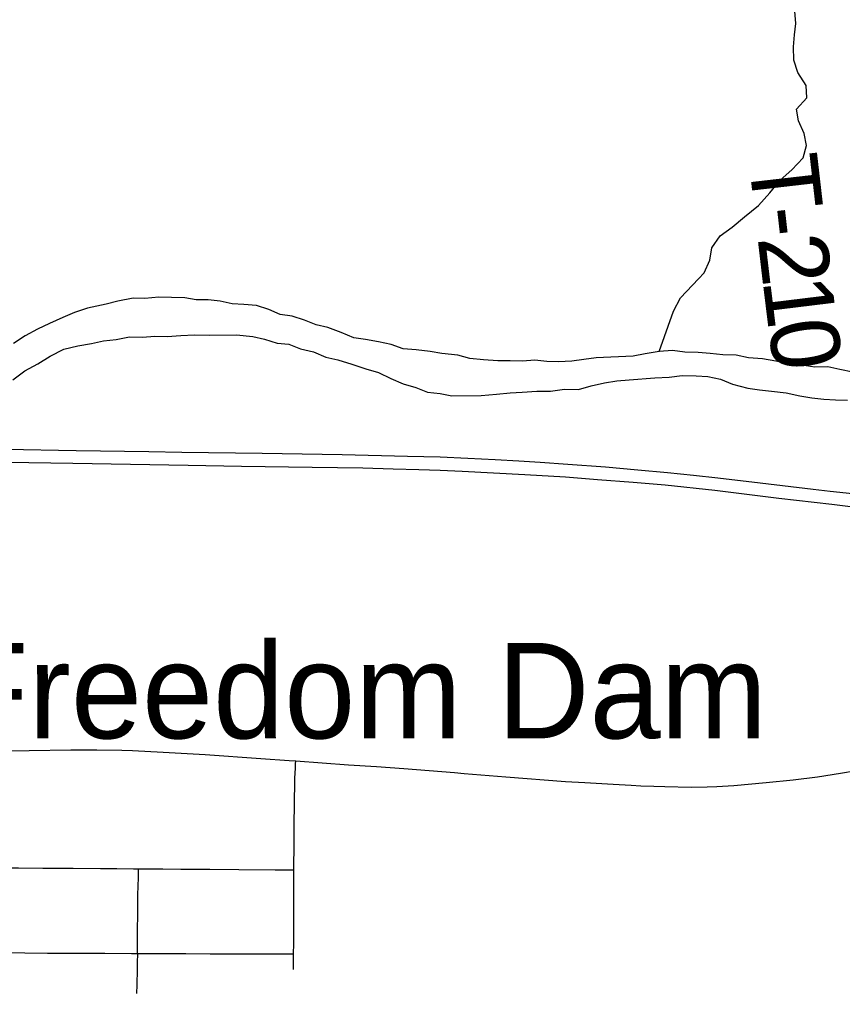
# Model space of a CAD drawing. Extents: x 0 to 34, y 0 to 22.
# Drawn here: x 14.031 to 14.711, y 18.319 to 19.125 of the extents above; entities that cross this region are included whole.
import ezdxf

# ---------------------------------------------------------------- set-up
doc = ezdxf.new("R2010")
doc.units = 0
for name, color, linetype in [('GM_X_Interstate_Route', 7, 'Continuous'), ('GM_X_Major_River', 7, 'Continuous'), ('GM_X_Minor_River', 7, 'Continuous'), ('GM_X_State_Route', 7, 'Continuous'), ('GM_X_Township_Road', 7, 'Continuous'), ('GM_X_Township_Road_Text', 7, 'Continuous'), ('GM_X_Unincorporated_Text', 7, 'Continuous')]:
    doc.layers.add(name, color=color, linetype=linetype)

msp = doc.modelspace()

# ---------------------------------------------------------------- linework, layer by layer
at = {"layer": 'GM_X_Interstate_Route'}
for points in [[(14.01976, 18.7694), (14.07788, 18.76845), (14.13792, 18.76746), (14.16514, 18.76709), (14.23153, 18.76605), (14.29764, 18.76501), (14.35159, 18.76379), (14.37868, 18.76305), (14.40152, 18.76197), (14.4241, 18.76092), (14.44354, 18.75971), (14.46118, 18.75865), (14.48406, 18.75715), (14.51516, 18.75474), (14.54207, 18.75248), (14.56644, 18.75023), (14.58797, 18.74798), (14.60815, 18.74572), (14.64314, 18.74167), (14.68695, 18.73642), (14.70095, 18.73479), (14.71924, 18.73266)], [(13.99038, 18.75888), (14.03863, 18.75832), (14.07493, 18.7579), (14.17041, 18.75624), (14.21428, 18.75549), (14.27278, 18.75462), (14.3148, 18.75392), (14.33985, 18.75324), (14.36103, 18.75261), (14.37867, 18.75209), (14.39666, 18.75136), (14.4486, 18.74848), (14.48222, 18.74644), (14.50857, 18.74428), (14.53819, 18.74205), (14.56458, 18.73985), (14.60559, 18.73563), (14.65837, 18.72905), (14.70224, 18.72398), (14.76361, 18.71623)]]:
    msp.add_lwpolyline(points, dxfattribs=at)
at = {"layer": 'GM_X_Major_River'}
for points in [[(14.24642, 18.88083), (14.23693, 18.88493), (14.22668, 18.88826), (14.21646, 18.88894), (14.20661, 18.88962), (14.19675, 18.89183), (14.1869, 18.89289), (14.17707, 18.89281), (14.16759, 18.89464), (14.15661, 18.89493), (14.14601, 18.89523), (14.13466, 18.89401), (14.12482, 18.89431), (14.11235, 18.89194), (14.10253, 18.88921), (14.08704, 18.88606), (14.07647, 18.88256), (14.06666, 18.87831), (14.05572, 18.8733), (14.04591, 18.86867), (14.03574, 18.86328), (14.02594, 18.85676)], [(14.71952, 18.83323), (14.70891, 18.83543), (14.69905, 18.83763), (14.68808, 18.83716), (14.67747, 18.83898), (14.6661, 18.84003), (14.65587, 18.84223), (14.64488, 18.84404), (14.63351, 18.84509), (14.62328, 18.84729), (14.6123, 18.84758), (14.60169, 18.84864), (14.59185, 18.84933), (14.58087, 18.84962), (14.57064, 18.85106), (14.55967, 18.85022), (14.54795, 18.84823), (14.53812, 18.84626), (14.50748, 18.84489), (14.49727, 18.84367), (14.48744, 18.84208), (14.47647, 18.84162), (14.46662, 18.84192), (14.45677, 18.84298), (14.44656, 18.84215), (14.43634, 18.84245), (14.42612, 18.84237), (14.41438, 18.84342), (14.40302, 18.84447), (14.39315, 18.84705), (14.3799, 18.84847), (14.37042, 18.85029), (14.35868, 18.85172), (14.34807, 18.8524), (14.3382, 18.85611), (14.32759, 18.85831), (14.31698, 18.86012), (14.30713, 18.86157), (14.29687, 18.86604), (14.28586, 18.87013), (14.27601, 18.87233), (14.26652, 18.87605), (14.25627, 18.87938), (14.24642, 18.88083)], [(14.02536, 18.8269), (14.0355, 18.83424), (14.04604, 18.84006), (14.0562, 18.84625), (14.0675, 18.85208), (14.07921, 18.85487), (14.09055, 18.85691), (14.10037, 18.85892), (14.11097, 18.86018), (14.12193, 18.86221), (14.13253, 18.86196), (14.14275, 18.86283), (14.15298, 18.86258), (14.16433, 18.86347), (14.17569, 18.86398), (14.18781, 18.86374), (14.21015, 18.864), (14.2238, 18.86264), (14.23329, 18.86047), (14.24394, 18.85718), (14.25342, 18.85615), (14.26331, 18.85247), (14.27394, 18.84994), (14.28422, 18.8455), (14.29409, 18.84333), (14.30549, 18.83967), (14.31727, 18.83601), (14.32753, 18.83271), (14.33781, 18.8279), (14.34809, 18.82346), (14.35835, 18.82054), (14.36824, 18.81648), (14.37848, 18.81546), (14.38835, 18.81367), (14.41258, 18.81396), (14.42507, 18.81486), (14.43642, 18.81614), (14.44626, 18.81663), (14.45837, 18.81753), (14.46973, 18.81728), (14.48146, 18.81894), (14.49282, 18.81869), (14.50339, 18.82185), (14.51435, 18.82426), (14.52456, 18.8259), (14.53477, 18.82678), (14.55597, 18.82854), (14.5677, 18.82906), (14.57867, 18.83033), (14.59003, 18.83008), (14.59989, 18.82944), (14.61014, 18.82728), (14.62003, 18.82322), (14.63295, 18.81995), (14.64243, 18.81854), (14.65229, 18.81752), (14.66442, 18.81614), (14.67581, 18.81361), (14.68568, 18.81183), (14.69554, 18.8108), (14.70539, 18.81016), (14.71525, 18.8099)]]:
    msp.add_lwpolyline(points, dxfattribs=at)
at = {"layer": 'GM_X_Minor_River'}
for points in [[(14.59209, 18.91033), (14.59687, 18.91536), (14.60137, 18.92562), (14.60322, 18.93588), (14.61, 18.94578), (14.61982, 18.95304), (14.63001, 18.96144), (14.64172, 18.97098), (14.65115, 18.98127), (14.65943, 18.99194), (14.66925, 19.00034), (14.67868, 19.01025), (14.68129, 19.02051), (14.67935, 19.03037), (14.67475, 19.04097), (14.67319, 19.05045), (14.68148, 19.05997), (14.68105, 19.07022), (14.67418, 19.08081), (14.67072, 19.09104), (14.67067, 19.10204), (14.67138, 19.11191), (14.67247, 19.1214), (14.67167, 19.13165)], [(14.55962, 18.85021), (14.57152, 18.88369), (14.57717, 18.89455), (14.59209, 18.91033)]]:
    msp.add_lwpolyline(points, dxfattribs=at)
at = {"layer": 'GM_X_State_Route'}
for points in [[(14.39854, 18.50129), (14.43284, 18.49839), (14.48204, 18.49478), (14.49807, 18.49378), (14.52156, 18.49242), (14.53645, 18.49161), (14.54451, 18.4911), (14.55505, 18.49066), (14.56436, 18.49041), (14.5861, 18.49005), (14.59912, 18.49014), (14.60716, 18.49042), (14.62139, 18.49136), (14.64797, 18.49374), (14.67021, 18.49592), (14.69052, 18.49854), (14.70955, 18.50148), (14.74815, 18.50804), (14.79592, 18.5163), (14.86532, 18.52858)], [(14.02413, 18.52007), (14.03905, 18.5204), (14.07325, 18.52078), (14.07884, 18.52074), (14.095, 18.52075), (14.11552, 18.52044), (14.12423, 18.52015), (14.14972, 18.51902), (14.17951, 18.51718)], [(14.17951, 18.51718), (14.18448, 18.51687), (14.23034, 18.51364), (14.2539, 18.51204), (14.25921, 18.51166)], [(14.25921, 18.51166), (14.30286, 18.5085), (14.32589, 18.50695), (14.34859, 18.50533), (14.39047, 18.50198), (14.39854, 18.50129)]]:
    msp.add_lwpolyline(points, dxfattribs=at)
at = {"layer": 'GM_X_Township_Road'}
for points in [[(14.25777, 18.42154), (14.25783, 18.44397), (14.25802, 18.45531), (14.25834, 18.47988), (14.25849, 18.4915), (14.25862, 18.49737), (14.2587, 18.50143), (14.25891, 18.50559), (14.25908, 18.50918), (14.25921, 18.51166)], [(13.98712, 18.42339), (13.99404, 18.42335), (14.00977, 18.42326), (14.03002, 18.42315), (14.05017, 18.42302), (14.07526, 18.42286), (14.098, 18.42272), (14.11127, 18.42263), (14.12511, 18.42251), (14.12932, 18.42248)], [(14.12846, 18.3524), (14.12853, 18.36223), (14.12861, 18.37245), (14.12866, 18.38401), (14.12872, 18.39624), (14.12883, 18.40242), (14.12895, 18.40675), (14.12918, 18.41652), (14.1293, 18.42134), (14.12932, 18.42248)], [(14.12932, 18.42248), (14.13542, 18.42245), (14.14954, 18.42239), (14.16416, 18.42226), (14.18837, 18.42205), (14.21215, 18.42187), (14.24226, 18.42165), (14.2566, 18.42154), (14.25777, 18.42154)], [(14.2575, 18.35203), (14.25757, 18.36042), (14.25761, 18.37148), (14.25767, 18.38736), (14.25774, 18.41373), (14.25777, 18.42154)], [(13.98672, 18.35334), (13.99478, 18.35328), (14.01735, 18.35312), (14.03543, 18.35298), (14.05399, 18.35284), (14.06785, 18.35279), (14.08353, 18.35274), (14.10152, 18.3526), (14.12362, 18.35243), (14.12846, 18.3524)], [(14.12799, 18.31934), (14.12812, 18.32653), (14.12835, 18.33931), (14.12841, 18.34598), (14.12882, 18.35099), (14.12846, 18.3524)], [(14.12846, 18.3524), (14.13353, 18.35238), (14.14054, 18.35236), (14.15341, 18.35234), (14.16843, 18.35231), (14.18856, 18.35227), (14.20473, 18.35222), (14.22858, 18.35214), (14.24574, 18.35207), (14.25631, 18.35204), (14.2575, 18.35203)], [(14.2573, 18.33915), (14.25747, 18.34908), (14.2575, 18.35203)]]:
    msp.add_lwpolyline(points, dxfattribs=at)

# ---------------------------------------------------------------- texts
at = {"layer": 'GM_X_Township_Road_Text'}
for s, rotation, p in [('T', 276.55837, (14.63333, 19.00987)), ('-', 276.5622, (14.63818, 18.96764)), ('2', 276.66483, (14.64086, 18.94435)), ('1', 276.98174, (14.64497, 18.90925)), ('0', 277.93661, (14.64935, 18.87348))]:
    msp.add_text(s, height=0.05682, rotation=rotation, dxfattribs=at).set_placement(p)
at = {"layer": 'GM_X_Unincorporated_Text'}
msp.add_text('Freedom Dam', height=0.0789773, rotation=0.00001, dxfattribs=at).set_placement((13.9738, 18.53031))

doc.saveas('drawing.dxf')
